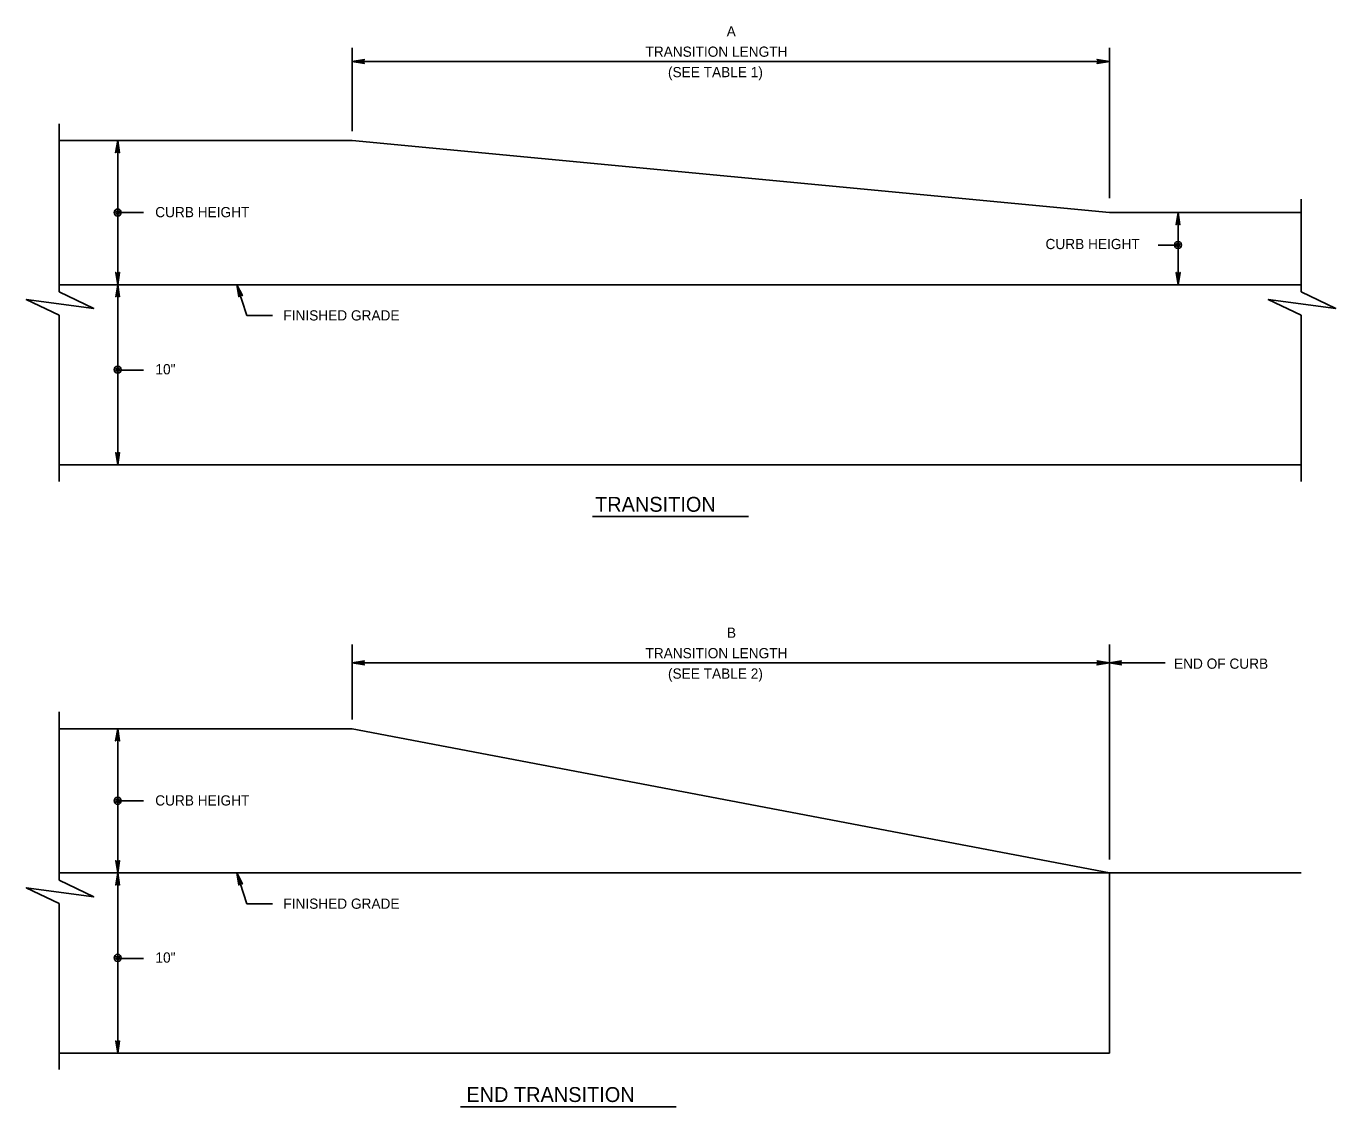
# Model space of a CAD drawing. Extents: x 2092490 to 2102560, y 980575 to 982524.
# Drawn here: x 2092490 to 2093701, y 981343 to 982343 of the extents above; entities that cross this region are included whole.
import ezdxf

# ---------------------------------------------------------------- set-up
doc = ezdxf.new("R2010")
doc.units = 0
doc.layers.add('2', color=7, linetype='Continuous')
doc.layers.add('3', color=7, linetype='Continuous')

msp = doc.modelspace()

# ---------------------------------------------------------------- linework, layer by layer
at = {"layer": '2'}
for p, q in [((2092791.9, 982322.9), (2092791.9, 982245.9)), ((2093491.9, 982322.9), (2093491.9, 982183.7)), ((2092520.9, 982237.2), (2092791.9, 982237.2)), ((2092575, 982237.2), (2092575, 981937.2)), ((2092791.9, 982237.2), (2093491.9, 982170.5)), ((2093491.9, 982170.5), (2093669.4, 982170.5)), ((2093555.4, 982170.5), (2093555.4, 982103.8)), ((2092520.9, 982103.8), (2093669.4, 982103.8)), ((2092520.9, 981937.2), (2093669.4, 981937.2)), ((2092791.9, 981771.1), (2092791.9, 981701.8)), ((2093491.9, 981771.1), (2093491.9, 981572.3)), ((2092520.9, 981693.1), (2092791.9, 981693.1)), ((2092575, 981693.1), (2092575, 981393.1)), ((2092791.9, 981693.1), (2093491.9, 981559.8)), ((2092520.9, 981559.8), (2093669.4, 981559.8)), ((2093491.9, 981559.8), (2093491.9, 981393.1)), ((2092520.9, 981393.1), (2093491.9, 981393.1))]:
    msp.add_line(p, q, dxfattribs=at)
at = {"layer": '3'}
for p, q in [((2092791.9, 982310.3), (2093491.9, 982310.3)), ((2092520.9, 982252.7), (2092520.9, 982097.3)), ((2093669.4, 982182.8), (2093669.4, 982097.3)), ((2092575, 982170.5), (2092599, 982170.5)), ((2093555.4, 982170.5), (2093579.4, 982170.5)), ((2093536.9, 982140.5), (2093555.4, 982140.5)), ((2092694.3, 982075.3), (2092685.2, 982103.8)), ((2092520.9, 982075.6), (2092520.9, 981921.8)), ((2092694.3, 982075.3), (2092718.3, 982075.3)), ((2093669.4, 982075.6), (2093669.4, 981921.8)), ((2092575, 982024.7), (2092599, 982024.7)), ((2093013.9, 981889.3), (2093158.2, 981889.3)), ((2092791.9, 981754), (2093543.5, 981754)), ((2092520.9, 981708.6), (2092520.9, 981553.2)), ((2092575, 981626.5), (2092599, 981626.5)), ((2092694.3, 981531.2), (2092685.2, 981559.8)), ((2092520.9, 981531.5), (2092520.9, 981377.8)), ((2092694.3, 981531.2), (2092718.3, 981531.2)), ((2092575, 981480.6), (2092599, 981480.6)), ((2092892.1, 981343.4), (2093091.5, 981343.4))]:
    msp.add_line(p, q, dxfattribs=at)
for points in [[(2092802.6, 982309), (2092802.2, 982309.7), (2092791.9, 982310.3), (2092802.6, 982309), (2092803.1, 982308.5), (2092791.9, 982310.3), (2092802.2, 982310.8), (2092802.5, 982311.6), (2092791.9, 982310.3), (2092803.1, 982312.1), (2092802.5, 982311.6)], [(2093481.1, 982309), (2093481.5, 982309.7), (2093491.9, 982310.3), (2093481.1, 982309), (2093480.6, 982308.5), (2093491.9, 982310.3), (2093481.5, 982310.8), (2093481.2, 982311.6), (2093491.9, 982310.3), (2093480.6, 982312.1), (2093481.2, 982311.6)], [(2092573.6, 982226.5), (2092574.4, 982226.9), (2092575, 982237.2), (2092573.6, 982226.5), (2092573.1, 982225.9), (2092575, 982237.2), (2092575.5, 982226.9), (2092576.2, 982226.5), (2092575, 982237.2), (2092576.8, 982225.9), (2092576.2, 982226.5)], [(2093554.1, 982159.8), (2093554.9, 982160.2), (2093555.4, 982170.5), (2093554.1, 982159.8), (2093553.6, 982159.2), (2093555.4, 982170.5), (2093556, 982160.2), (2093556.7, 982159.8), (2093555.4, 982170.5), (2093557.2, 982159.2), (2093556.7, 982159.8)], [(2092576.3, 982114.6), (2092575.5, 982114.2), (2092575, 982103.8), (2092576.3, 982114.6), (2092576.8, 982115.1), (2092575, 982103.8), (2092574.5, 982114.2), (2092573.7, 982114.5), (2092575, 982103.8), (2092573.2, 982115.1), (2092573.7, 982114.5)], [(2093556.8, 982114.6), (2093556, 982114.2), (2093555.4, 982103.8), (2093556.8, 982114.6), (2093557.3, 982115.1), (2093555.4, 982103.8), (2093554.9, 982114.2), (2093554.2, 982114.5), (2093555.4, 982103.8), (2093553.7, 982115.1), (2093554.2, 982114.5)], [(2092576.3, 982093.1), (2092575.5, 982093.5), (2092575, 982103.8), (2092576.3, 982093.1), (2092576.8, 982092.6), (2092575, 982103.8), (2092574.5, 982093.5), (2092573.7, 982093.1), (2092575, 982103.8), (2092573.2, 982092.6), (2092573.7, 982093.1)], [(2092687.3, 982093.2), (2092687.9, 982093.9), (2092685.2, 982103.8), (2092687.3, 982093.2), (2092687, 982092.6), (2092685.2, 982103.8), (2092688.9, 982094.2), (2092689.8, 982094.1), (2092685.2, 982103.8), (2092690.4, 982093.7), (2092689.8, 982094.1)], [(2092520.9, 982097.3), (2092552.8, 982081.7), (2092490.4, 982090.1), (2092520.9, 982075.6)], [(2093669.4, 982097.3), (2093701.3, 982081.7), (2093638.9, 982090.1), (2093669.4, 982075.6)], [(2092576.3, 981947.9), (2092575.5, 981947.5), (2092575, 981937.2), (2092576.3, 981947.9), (2092576.8, 981948.5), (2092575, 981937.2), (2092574.5, 981947.5), (2092573.7, 981947.9), (2092575, 981937.2), (2092573.2, 981948.5), (2092573.7, 981947.9)], [(2092802.6, 981752.7), (2092802.2, 981753.4), (2092791.9, 981754), (2092802.6, 981752.7), (2092803.1, 981752.2), (2092791.9, 981754), (2092802.2, 981754.5), (2092802.5, 981755.3), (2092791.9, 981754), (2092803.1, 981755.8), (2092802.5, 981755.3)], [(2093481.1, 981752.7), (2093481.5, 981753.4), (2093491.9, 981754), (2093481.1, 981752.7), (2093480.6, 981752.2), (2093491.9, 981754), (2093481.5, 981754.5), (2093481.2, 981755.3), (2093491.9, 981754), (2093480.6, 981755.8), (2093481.2, 981755.3)], [(2093502.6, 981752.7), (2093502.2, 981753.4), (2093491.9, 981754), (2093502.6, 981752.7), (2093503.1, 981752.2), (2093491.9, 981754), (2093502.2, 981754.5), (2093502.5, 981755.3), (2093491.9, 981754), (2093503.1, 981755.8), (2093502.5, 981755.3)], [(2092573.6, 981682.4), (2092574.4, 981682.8), (2092575, 981693.1), (2092573.6, 981682.4), (2092573.1, 981681.8), (2092575, 981693.1), (2092575.5, 981682.8), (2092576.2, 981682.4), (2092575, 981693.1), (2092576.8, 981681.8), (2092576.2, 981682.4)], [(2092576.3, 981570.5), (2092575.5, 981570.1), (2092575, 981559.8), (2092576.3, 981570.5), (2092576.8, 981571), (2092575, 981559.8), (2092574.5, 981570.1), (2092573.7, 981570.5), (2092575, 981559.8), (2092573.2, 981571), (2092573.7, 981570.5)], [(2092520.9, 981553.2), (2092552.8, 981537.6), (2092490.4, 981546.1), (2092520.9, 981531.5)], [(2092576.3, 981549), (2092575.5, 981549.4), (2092575, 981559.8), (2092576.3, 981549), (2092576.8, 981548.5), (2092575, 981559.8), (2092574.5, 981549.5), (2092573.7, 981549.1), (2092575, 981559.8), (2092573.2, 981548.5), (2092573.7, 981549.1)], [(2092687.3, 981549.2), (2092687.9, 981549.8), (2092685.2, 981559.8), (2092687.3, 981549.2), (2092687, 981548.5), (2092685.2, 981559.8), (2092688.9, 981550.1), (2092689.8, 981550), (2092685.2, 981559.8), (2092690.4, 981549.6), (2092689.8, 981550)], [(2092576.3, 981403.8), (2092575.5, 981403.4), (2092575, 981393.1), (2092576.3, 981403.8), (2092576.8, 981404.4), (2092575, 981393.1), (2092574.5, 981403.4), (2092573.7, 981403.8), (2092575, 981393.1), (2092573.2, 981404.4), (2092573.7, 981403.8)]]:
    msp.add_lwpolyline(points, dxfattribs=at)
for centre, radius in [((2092575, 982170.5), 3.28), ((2092575, 982170.5), 1.64), ((2093555.4, 982140.5), 3.28), ((2093555.4, 982140.5), 1.64), ((2092575, 982025.2), 3.28), ((2092575, 982025.2), 1.64), ((2092575, 981626.5), 3.28), ((2092575, 981626.5), 1.64), ((2092575, 981481.2), 3.28), ((2092575, 981481.2), 1.64)]:
    msp.add_circle(centre, radius, dxfattribs=at)

# ---------------------------------------------------------------- texts
for s, height, p in [('A', 9.45, (2093138.1, 982333.4)), ('TRANSITION LENGTH', 9.449, (2093063, 982314.6)), ('(SEE TABLE 1)', 9.449, (2093083.8, 982295.7)), ('CURB HEIGHT', 9.449, (2092609.7, 982166.2)), ('CURB HEIGHT', 9.449, (2093432.9, 982136.7)), ('FINISHED GRADE', 9.449, (2092728.2, 982070.7)), ('10"', 9.45, (2092609.9, 982020.9)), ('TRANSITION', 13.78, (2093016.4, 981893.8)), ('B', 9.45, (2093138.3, 981777.2)), ('TRANSITION LENGTH', 9.449, (2093063, 981758.3)), ('(SEE TABLE 2)', 9.449, (2093083.8, 981739.4)), ('END OF CURB', 9.449, (2093551.7, 981748.6)), ('CURB HEIGHT', 9.449, (2092609.7, 981622.1)), ('FINISHED GRADE', 9.449, (2092728.2, 981526.6)), ('10"', 9.45, (2092609.9, 981476.8)), ('END TRANSITION', 13.78, (2092897.4, 981347.9))]:
    msp.add_text(s, height=height, dxfattribs=at).set_placement(p)

doc.saveas('drawing.dxf')
